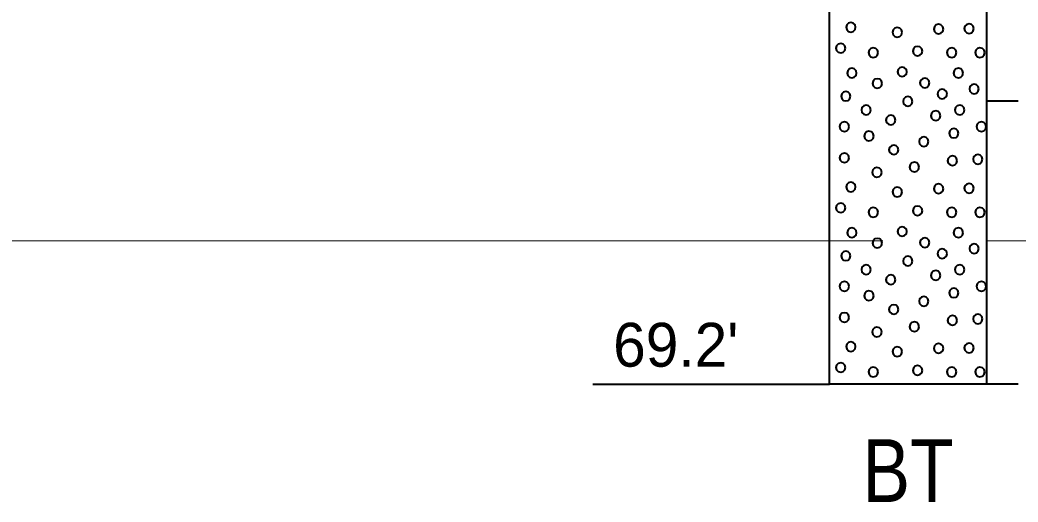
# Model space of a CAD drawing. Extents: x -582 to 653, y -817 to -3.
# Drawn here: x 14.65 to 30.53, y -558.29 to -550.62 of the extents above; entities that cross this region are included whole.
import ezdxf
from ezdxf.enums import TextEntityAlignment as Align

# ---------------------------------------------------------------- set-up
doc = ezdxf.new("R2010")
doc.units = 0
doc.header["$LTSCALE"] = 0.4
doc.layers.add('27', color=7, linetype='Continuous', lineweight=40)
doc.layers.add('7', color=7, linetype='Continuous', lineweight=13)

msp = doc.modelspace()

# ---------------------------------------------------------------- linework, layer by layer
at = {"layer": '27'}
for p, q in [((30.5287, -551.9128), (30.0287, -551.9128)), ((23.7613, -556.4128), (27.5287, -556.4128)), ((30.5287, -556.4128), (30.0287, -556.4128))]:
    msp.add_line(p, q, dxfattribs=at)
for points in [[(27.5287, -548.7128), (30.0287, -548.7128), (30.0287, -556.4128), (27.5287, -556.4128)], [(27.9445, -550.7362), (27.9343, -550.6981), (27.9064, -550.6702), (27.8683, -550.66), (27.8302, -550.6702), (27.8023, -550.6981), (27.7921, -550.7362), (27.8023, -550.7743), (27.8302, -550.8022), (27.8683, -550.8124), (27.9064, -550.8022), (27.9343, -550.7743)], [(28.6831, -550.8163), (28.6729, -550.7782), (28.645, -550.7503), (28.6069, -550.7401), (28.5688, -550.7503), (28.5409, -550.7782), (28.5307, -550.8163), (28.5409, -550.8544), (28.5688, -550.8823), (28.6069, -550.8925), (28.645, -550.8823), (28.6729, -550.8544)], [(29.3403, -550.7654), (29.3301, -550.7273), (29.3022, -550.6994), (29.2641, -550.6892), (29.226, -550.6994), (29.1982, -550.7273), (29.1879, -550.7654), (29.1982, -550.8035), (29.226, -550.8314), (29.2641, -550.8416), (29.3022, -550.8314), (29.3301, -550.8035)], [(29.826, -550.7578), (29.8158, -550.7197), (29.7879, -550.6918), (29.7498, -550.6816), (29.7117, -550.6918), (29.6838, -550.7197), (29.6736, -550.7578), (29.6838, -550.7959), (29.7117, -550.8238), (29.7498, -550.834), (29.7879, -550.8238), (29.8158, -550.7959)], [(27.783, -551.0693), (27.7728, -551.0312), (27.7449, -551.0033), (27.7068, -550.9931), (27.6687, -551.0033), (27.6408, -551.0312), (27.6306, -551.0693), (27.6408, -551.1074), (27.6687, -551.1353), (27.7068, -551.1455), (27.7449, -551.1353), (27.7728, -551.1074)], [(28.3017, -551.1392), (28.2915, -551.1011), (28.2636, -551.0732), (28.2255, -551.063), (28.1874, -551.0732), (28.1595, -551.1011), (28.1493, -551.1392), (28.1595, -551.1773), (28.1874, -551.2052), (28.2255, -551.2154), (28.2636, -551.2052), (28.2915, -551.1773)], [(29.006, -551.1163), (28.9958, -551.0782), (28.9679, -551.0503), (28.9298, -551.0401), (28.8917, -551.0503), (28.8638, -551.0782), (28.8536, -551.1163), (28.8638, -551.1544), (28.8917, -551.1823), (28.9298, -551.1925), (28.9679, -551.1823), (28.9958, -551.1544)], [(29.5488, -551.1392), (29.5386, -551.1011), (29.5107, -551.0732), (29.4726, -551.063), (29.4345, -551.0732), (29.4066, -551.1011), (29.3964, -551.1392), (29.4066, -551.1773), (29.4345, -551.2052), (29.4726, -551.2154), (29.5107, -551.2052), (29.5386, -551.1773)], [(29.9989, -551.1392), (29.9887, -551.1011), (29.9608, -551.0732), (29.9227, -551.063), (29.8846, -551.0732), (29.8567, -551.1011), (29.8465, -551.1392), (29.8567, -551.1773), (29.8846, -551.2052), (29.9227, -551.2154), (29.9608, -551.2052), (29.9887, -551.1773)], [(27.9606, -551.4655), (27.9504, -551.4274), (27.9225, -551.3995), (27.8844, -551.3893), (27.8463, -551.3995), (27.8184, -551.4274), (27.8082, -551.4655), (27.8184, -551.5036), (27.8463, -551.5314), (27.8844, -551.5417), (27.9225, -551.5314), (27.9504, -551.5036)], [(28.7616, -551.4459), (28.7513, -551.4078), (28.7235, -551.3799), (28.6854, -551.3697), (28.6473, -551.3799), (28.6194, -551.4078), (28.6092, -551.4459), (28.6194, -551.484), (28.6473, -551.5119), (28.6854, -551.5221), (28.7235, -551.5119), (28.7513, -551.484)], [(29.6552, -551.4655), (29.645, -551.4274), (29.6171, -551.3995), (29.579, -551.3893), (29.5409, -551.3995), (29.513, -551.4274), (29.5028, -551.4655), (29.513, -551.5036), (29.5409, -551.5315), (29.579, -551.5417), (29.6171, -551.5315), (29.645, -551.5036)], [(28.3655, -551.6307), (28.3553, -551.5926), (28.3274, -551.5647), (28.2893, -551.5545), (28.2512, -551.5647), (28.2233, -551.5926), (28.2131, -551.6307), (28.2233, -551.6688), (28.2512, -551.6967), (28.2893, -551.7069), (28.3274, -551.6967), (28.3553, -551.6688)], [(29.1206, -551.6217), (29.1104, -551.5836), (29.0825, -551.5557), (29.0444, -551.5455), (29.0063, -551.5557), (28.9784, -551.5836), (28.9682, -551.6217), (28.9784, -551.6598), (29.0063, -551.6877), (29.0444, -551.6979), (29.0825, -551.6877), (29.1104, -551.6598)], [(27.8644, -551.8333), (27.8542, -551.7952), (27.8263, -551.7673), (27.7882, -551.7571), (27.7501, -551.7673), (27.7222, -551.7952), (27.712, -551.8333), (27.7222, -551.8714), (27.7501, -551.8993), (27.7882, -551.9095), (27.8263, -551.8993), (27.8542, -551.8714)], [(29.3988, -551.799), (29.3886, -551.7609), (29.3607, -551.733), (29.3226, -551.7228), (29.2845, -551.733), (29.2566, -551.7609), (29.2464, -551.799), (29.2566, -551.8371), (29.2845, -551.865), (29.3226, -551.8752), (29.3607, -551.865), (29.3886, -551.8371)], [(29.9061, -551.7176), (29.8959, -551.6795), (29.868, -551.6516), (29.8299, -551.6414), (29.7918, -551.6516), (29.7639, -551.6795), (29.7537, -551.7176), (29.7639, -551.7557), (29.7918, -551.7836), (29.8299, -551.7938), (29.868, -551.7836), (29.8959, -551.7557)], [(28.8505, -551.9165), (28.8403, -551.8784), (28.8124, -551.8505), (28.7743, -551.8403), (28.7362, -551.8505), (28.7083, -551.8784), (28.6981, -551.9165), (28.7083, -551.9546), (28.7362, -551.9825), (28.7743, -551.9927), (28.8124, -551.9825), (28.8403, -551.9546)], [(28.1873, -552.052), (28.1771, -552.0139), (28.1492, -551.986), (28.1111, -551.9758), (28.073, -551.986), (28.0451, -552.0139), (28.0349, -552.052), (28.0451, -552.0901), (28.073, -552.118), (28.1111, -552.1282), (28.1492, -552.118), (28.1771, -552.0901)], [(29.2946, -552.1448), (29.2844, -552.1067), (29.2565, -552.0788), (29.2184, -552.0686), (29.1803, -552.0788), (29.1524, -552.1067), (29.1422, -552.1448), (29.1524, -552.1829), (29.1803, -552.2108), (29.2184, -552.221), (29.2565, -552.2108), (29.2844, -552.1829)], [(29.676, -552.052), (29.6658, -552.0139), (29.6379, -551.986), (29.5998, -551.9758), (29.5617, -551.986), (29.5338, -552.0139), (29.5236, -552.052), (29.5338, -552.0901), (29.5617, -552.118), (29.5998, -552.1282), (29.6379, -552.118), (29.6658, -552.0901)], [(27.8415, -552.3177), (27.8313, -552.2796), (27.8034, -552.2517), (27.7653, -552.2415), (27.7272, -552.2517), (27.6993, -552.2796), (27.6891, -552.3177), (27.6993, -552.3558), (27.7272, -552.3837), (27.7653, -552.3939), (27.8034, -552.3837), (27.8313, -552.3558)], [(28.5789, -552.2134), (28.5686, -552.1753), (28.5408, -552.1474), (28.5027, -552.1372), (28.4646, -552.1474), (28.4367, -552.1753), (28.4265, -552.2134), (28.4367, -552.2515), (28.4646, -552.2794), (28.5027, -552.2896), (28.5408, -552.2794), (28.5686, -552.2515)], [(30.0217, -552.3177), (30.0115, -552.2796), (29.9836, -552.2517), (29.9455, -552.2415), (29.9074, -552.2517), (29.8796, -552.2796), (29.8693, -552.3177), (29.8796, -552.3558), (29.9074, -552.3837), (29.9455, -552.3939), (29.9836, -552.3837), (30.0115, -552.3558)], [(28.2331, -552.4677), (28.2229, -552.4296), (28.195, -552.4017), (28.1569, -552.3915), (28.1188, -552.4017), (28.0909, -552.4296), (28.0807, -552.4677), (28.0909, -552.5058), (28.1188, -552.5337), (28.1569, -552.5439), (28.195, -552.5337), (28.2229, -552.5058)], [(29.5832, -552.4219), (29.5729, -552.3838), (29.5451, -552.3559), (29.507, -552.3457), (29.4689, -552.3559), (29.441, -552.3838), (29.4308, -552.4219), (29.441, -552.46), (29.4689, -552.4879), (29.507, -552.4981), (29.5451, -552.4879), (29.5729, -552.46)], [(29.1052, -552.5554), (29.095, -552.5173), (29.0671, -552.4894), (29.029, -552.4792), (28.9909, -552.4894), (28.963, -552.5173), (28.9528, -552.5554), (28.963, -552.5935), (28.9909, -552.6214), (29.029, -552.6316), (29.0671, -552.6214), (29.095, -552.5935)], [(27.8415, -552.8135), (27.8313, -552.7754), (27.8034, -552.7475), (27.7653, -552.7373), (27.7272, -552.7475), (27.6993, -552.7754), (27.6891, -552.8135), (27.6993, -552.8516), (27.7272, -552.8794), (27.7653, -552.8897), (27.8034, -552.8794), (27.8313, -552.8516)], [(28.6272, -552.6863), (28.617, -552.6482), (28.5891, -552.6203), (28.551, -552.6101), (28.5129, -552.6203), (28.485, -552.6482), (28.4748, -552.6863), (28.485, -552.7244), (28.5129, -552.7523), (28.551, -552.7625), (28.5891, -552.7523), (28.617, -552.7244)], [(28.9551, -552.9609), (28.9449, -552.9228), (28.917, -552.8949), (28.8789, -552.8847), (28.8408, -552.8949), (28.813, -552.9228), (28.8027, -552.9609), (28.813, -552.999), (28.8408, -553.0269), (28.8789, -553.0371), (28.917, -553.0269), (28.9449, -552.999)], [(29.5603, -552.8605), (29.5501, -552.8224), (29.5222, -552.7945), (29.4841, -552.7843), (29.446, -552.7945), (29.4181, -552.8224), (29.4079, -552.8605), (29.4181, -552.8986), (29.446, -552.9265), (29.4841, -552.9367), (29.5222, -552.9265), (29.5501, -552.8986)], [(29.9645, -552.8363), (29.9543, -552.7982), (29.9264, -552.7704), (29.8883, -552.7601), (29.8502, -552.7704), (29.8223, -552.7982), (29.8121, -552.8363), (29.8223, -552.8744), (29.8502, -552.9023), (29.8883, -552.9125), (29.9264, -552.9023), (29.9543, -552.8744)], [(28.3602, -553.0448), (28.35, -553.0067), (28.3221, -552.9788), (28.284, -552.9686), (28.2459, -552.9788), (28.218, -553.0067), (28.2078, -553.0448), (28.218, -553.0829), (28.2459, -553.1108), (28.284, -553.121), (28.3221, -553.1108), (28.35, -553.0829)], [(27.9445, -553.2762), (27.9343, -553.2381), (27.9064, -553.2102), (27.8683, -553.2), (27.8302, -553.2102), (27.8023, -553.2381), (27.7921, -553.2762), (27.8023, -553.3143), (27.8302, -553.3422), (27.8683, -553.3524), (27.9064, -553.3422), (27.9343, -553.3143)], [(28.6831, -553.3563), (28.6729, -553.3182), (28.645, -553.2903), (28.6069, -553.2801), (28.5688, -553.2903), (28.5409, -553.3182), (28.5307, -553.3563), (28.5409, -553.3944), (28.5688, -553.4223), (28.6069, -553.4325), (28.645, -553.4223), (28.6729, -553.3944)], [(29.3403, -553.3054), (29.3301, -553.2673), (29.3022, -553.2394), (29.2641, -553.2292), (29.226, -553.2394), (29.1982, -553.2673), (29.1879, -553.3054), (29.1982, -553.3435), (29.226, -553.3714), (29.2641, -553.3816), (29.3022, -553.3714), (29.3301, -553.3435)], [(29.826, -553.2978), (29.8158, -553.2597), (29.7879, -553.2318), (29.7498, -553.2216), (29.7117, -553.2318), (29.6838, -553.2597), (29.6736, -553.2978), (29.6838, -553.3359), (29.7117, -553.3638), (29.7498, -553.374), (29.7879, -553.3638), (29.8158, -553.3359)], [(27.783, -553.6093), (27.7728, -553.5712), (27.7449, -553.5433), (27.7068, -553.5331), (27.6687, -553.5433), (27.6408, -553.5712), (27.6306, -553.6093), (27.6408, -553.6474), (27.6687, -553.6753), (27.7068, -553.6855), (27.7449, -553.6753), (27.7728, -553.6474)], [(28.3017, -553.6792), (28.2915, -553.6411), (28.2636, -553.6132), (28.2255, -553.603), (28.1874, -553.6132), (28.1595, -553.6411), (28.1493, -553.6792), (28.1595, -553.7173), (28.1874, -553.7452), (28.2255, -553.7554), (28.2636, -553.7452), (28.2915, -553.7173)], [(29.006, -553.6563), (28.9958, -553.6182), (28.9679, -553.5903), (28.9298, -553.5801), (28.8917, -553.5903), (28.8638, -553.6182), (28.8536, -553.6563), (28.8638, -553.6944), (28.8917, -553.7223), (28.9298, -553.7325), (28.9679, -553.7223), (28.9958, -553.6944)], [(29.5488, -553.6792), (29.5386, -553.6411), (29.5107, -553.6132), (29.4726, -553.603), (29.4345, -553.6132), (29.4066, -553.6411), (29.3964, -553.6792), (29.4066, -553.7173), (29.4345, -553.7452), (29.4726, -553.7554), (29.5107, -553.7452), (29.5386, -553.7173)], [(29.9989, -553.6792), (29.9887, -553.6411), (29.9608, -553.6132), (29.9227, -553.603), (29.8846, -553.6132), (29.8567, -553.6411), (29.8465, -553.6792), (29.8567, -553.7173), (29.8846, -553.7452), (29.9227, -553.7554), (29.9608, -553.7452), (29.9887, -553.7173)], [(27.9606, -554.0055), (27.9504, -553.9674), (27.9225, -553.9395), (27.8844, -553.9293), (27.8463, -553.9395), (27.8184, -553.9674), (27.8082, -554.0055), (27.8184, -554.0436), (27.8463, -554.0714), (27.8844, -554.0817), (27.9225, -554.0714), (27.9504, -554.0436)], [(28.7616, -553.9859), (28.7513, -553.9478), (28.7235, -553.9199), (28.6854, -553.9097), (28.6473, -553.9199), (28.6194, -553.9478), (28.6092, -553.9859), (28.6194, -554.024), (28.6473, -554.0519), (28.6854, -554.0621), (28.7235, -554.0519), (28.7513, -554.024)], [(29.6552, -554.0055), (29.645, -553.9674), (29.6171, -553.9395), (29.579, -553.9293), (29.5409, -553.9395), (29.513, -553.9674), (29.5028, -554.0055), (29.513, -554.0436), (29.5409, -554.0715), (29.579, -554.0817), (29.6171, -554.0715), (29.645, -554.0436)], [(28.3655, -554.1707), (28.3553, -554.1326), (28.3274, -554.1047), (28.2893, -554.0945), (28.2512, -554.1047), (28.2233, -554.1326), (28.2131, -554.1707), (28.2233, -554.2088), (28.2512, -554.2367), (28.2893, -554.2469), (28.3274, -554.2367), (28.3553, -554.2088)], [(29.1206, -554.1617), (29.1104, -554.1236), (29.0825, -554.0957), (29.0444, -554.0855), (29.0063, -554.0957), (28.9784, -554.1236), (28.9682, -554.1617), (28.9784, -554.1998), (29.0063, -554.2277), (29.0444, -554.2379), (29.0825, -554.2277), (29.1104, -554.1998)], [(27.8644, -554.3733), (27.8542, -554.3352), (27.8263, -554.3073), (27.7882, -554.2971), (27.7501, -554.3073), (27.7222, -554.3352), (27.712, -554.3733), (27.7222, -554.4114), (27.7501, -554.4393), (27.7882, -554.4495), (27.8263, -554.4393), (27.8542, -554.4114)], [(29.3988, -554.339), (29.3886, -554.3009), (29.3607, -554.273), (29.3226, -554.2628), (29.2845, -554.273), (29.2566, -554.3009), (29.2464, -554.339), (29.2566, -554.3771), (29.2845, -554.405), (29.3226, -554.4152), (29.3607, -554.405), (29.3886, -554.3771)], [(29.9061, -554.2576), (29.8959, -554.2195), (29.868, -554.1916), (29.8299, -554.1814), (29.7918, -554.1916), (29.7639, -554.2195), (29.7537, -554.2576), (29.7639, -554.2957), (29.7918, -554.3236), (29.8299, -554.3338), (29.868, -554.3236), (29.8959, -554.2957)], [(28.8505, -554.4565), (28.8403, -554.4184), (28.8124, -554.3905), (28.7743, -554.3803), (28.7362, -554.3905), (28.7083, -554.4184), (28.6981, -554.4565), (28.7083, -554.4946), (28.7362, -554.5225), (28.7743, -554.5327), (28.8124, -554.5225), (28.8403, -554.4946)], [(28.1873, -554.592), (28.1771, -554.5539), (28.1492, -554.526), (28.1111, -554.5158), (28.073, -554.526), (28.0451, -554.5539), (28.0349, -554.592), (28.0451, -554.6301), (28.073, -554.658), (28.1111, -554.6682), (28.1492, -554.658), (28.1771, -554.6301)], [(29.2946, -554.6848), (29.2844, -554.6467), (29.2565, -554.6188), (29.2184, -554.6086), (29.1803, -554.6188), (29.1524, -554.6467), (29.1422, -554.6848), (29.1524, -554.7229), (29.1803, -554.7508), (29.2184, -554.761), (29.2565, -554.7508), (29.2844, -554.7229)], [(29.676, -554.592), (29.6658, -554.5539), (29.6379, -554.526), (29.5998, -554.5158), (29.5617, -554.526), (29.5338, -554.5539), (29.5236, -554.592), (29.5338, -554.6301), (29.5617, -554.658), (29.5998, -554.6682), (29.6379, -554.658), (29.6658, -554.6301)], [(27.8415, -554.8577), (27.8313, -554.8196), (27.8034, -554.7917), (27.7653, -554.7815), (27.7272, -554.7917), (27.6993, -554.8196), (27.6891, -554.8577), (27.6993, -554.8958), (27.7272, -554.9237), (27.7653, -554.9339), (27.8034, -554.9237), (27.8313, -554.8958)], [(28.5789, -554.7534), (28.5686, -554.7153), (28.5408, -554.6874), (28.5027, -554.6772), (28.4646, -554.6874), (28.4367, -554.7153), (28.4265, -554.7534), (28.4367, -554.7915), (28.4646, -554.8194), (28.5027, -554.8296), (28.5408, -554.8194), (28.5686, -554.7915)], [(30.0217, -554.8577), (30.0115, -554.8196), (29.9836, -554.7917), (29.9455, -554.7815), (29.9074, -554.7917), (29.8796, -554.8196), (29.8693, -554.8577), (29.8796, -554.8958), (29.9074, -554.9237), (29.9455, -554.9339), (29.9836, -554.9237), (30.0115, -554.8958)], [(28.2331, -555.0077), (28.2229, -554.9696), (28.195, -554.9417), (28.1569, -554.9315), (28.1188, -554.9417), (28.0909, -554.9696), (28.0807, -555.0077), (28.0909, -555.0458), (28.1188, -555.0737), (28.1569, -555.0839), (28.195, -555.0737), (28.2229, -555.0458)], [(29.5832, -554.9619), (29.5729, -554.9238), (29.5451, -554.8959), (29.507, -554.8857), (29.4689, -554.8959), (29.441, -554.9238), (29.4308, -554.9619), (29.441, -555), (29.4689, -555.0279), (29.507, -555.0381), (29.5451, -555.0279), (29.5729, -555)], [(29.1052, -555.0954), (29.095, -555.0573), (29.0671, -555.0294), (29.029, -555.0192), (28.9909, -555.0294), (28.963, -555.0573), (28.9528, -555.0954), (28.963, -555.1335), (28.9909, -555.1614), (29.029, -555.1716), (29.0671, -555.1614), (29.095, -555.1335)], [(27.8415, -555.3535), (27.8313, -555.3154), (27.8034, -555.2875), (27.7653, -555.2773), (27.7272, -555.2875), (27.6993, -555.3154), (27.6891, -555.3535), (27.6993, -555.3916), (27.7272, -555.4194), (27.7653, -555.4297), (27.8034, -555.4194), (27.8313, -555.3916)], [(28.6272, -555.2263), (28.617, -555.1882), (28.5891, -555.1603), (28.551, -555.1501), (28.5129, -555.1603), (28.485, -555.1882), (28.4748, -555.2263), (28.485, -555.2644), (28.5129, -555.2923), (28.551, -555.3025), (28.5891, -555.2923), (28.617, -555.2644)], [(28.9551, -555.5009), (28.9449, -555.4628), (28.917, -555.4349), (28.8789, -555.4247), (28.8408, -555.4349), (28.813, -555.4628), (28.8027, -555.5009), (28.813, -555.539), (28.8408, -555.5669), (28.8789, -555.5771), (28.917, -555.5669), (28.9449, -555.539)], [(29.5603, -555.4005), (29.5501, -555.3624), (29.5222, -555.3345), (29.4841, -555.3243), (29.446, -555.3345), (29.4181, -555.3624), (29.4079, -555.4005), (29.4181, -555.4386), (29.446, -555.4665), (29.4841, -555.4767), (29.5222, -555.4665), (29.5501, -555.4386)], [(29.9645, -555.3763), (29.9543, -555.3382), (29.9264, -555.3104), (29.8883, -555.3001), (29.8502, -555.3104), (29.8223, -555.3382), (29.8121, -555.3763), (29.8223, -555.4144), (29.8502, -555.4423), (29.8883, -555.4525), (29.9264, -555.4423), (29.9543, -555.4144)], [(28.3602, -555.5848), (28.35, -555.5467), (28.3221, -555.5188), (28.284, -555.5086), (28.2459, -555.5188), (28.218, -555.5467), (28.2078, -555.5848), (28.218, -555.6229), (28.2459, -555.6508), (28.284, -555.661), (28.3221, -555.6508), (28.35, -555.6229)], [(27.9445, -555.8162), (27.9343, -555.7781), (27.9064, -555.7502), (27.8683, -555.74), (27.8302, -555.7502), (27.8023, -555.7781), (27.7921, -555.8162), (27.8023, -555.8543), (27.8302, -555.8822), (27.8683, -555.8924), (27.9064, -555.8822), (27.9343, -555.8543)], [(29.826, -555.8378), (29.8158, -555.7997), (29.7879, -555.7718), (29.7498, -555.7616), (29.7117, -555.7718), (29.6838, -555.7997), (29.6736, -555.8378), (29.6838, -555.8759), (29.7117, -555.9038), (29.7498, -555.914), (29.7879, -555.9038), (29.8158, -555.8759)], [(28.6831, -555.8963), (28.6729, -555.8582), (28.645, -555.8303), (28.6069, -555.8201), (28.5688, -555.8303), (28.5409, -555.8582), (28.5307, -555.8963), (28.5409, -555.9344), (28.5688, -555.9623), (28.6069, -555.9725), (28.645, -555.9623), (28.6729, -555.9344)], [(29.3403, -555.8454), (29.3301, -555.8073), (29.3022, -555.7794), (29.2641, -555.7692), (29.226, -555.7794), (29.1982, -555.8073), (29.1879, -555.8454), (29.1982, -555.8835), (29.226, -555.9114), (29.2641, -555.9216), (29.3022, -555.9114), (29.3301, -555.8835)], [(27.783, -556.1493), (27.7728, -556.1112), (27.7449, -556.0833), (27.7068, -556.0731), (27.6687, -556.0833), (27.6408, -556.1112), (27.6306, -556.1493), (27.6408, -556.1874), (27.6687, -556.2153), (27.7068, -556.2255), (27.7449, -556.2153), (27.7728, -556.1874)], [(28.3017, -556.2192), (28.2915, -556.1811), (28.2636, -556.1532), (28.2255, -556.143), (28.1874, -556.1532), (28.1595, -556.1811), (28.1493, -556.2192), (28.1595, -556.2573), (28.1874, -556.2852), (28.2255, -556.2954), (28.2636, -556.2852), (28.2915, -556.2573)], [(29.006, -556.1963), (28.9958, -556.1582), (28.9679, -556.1303), (28.9298, -556.1201), (28.8917, -556.1303), (28.8638, -556.1582), (28.8536, -556.1963), (28.8638, -556.2344), (28.8917, -556.2623), (28.9298, -556.2725), (28.9679, -556.2623), (28.9958, -556.2344)], [(29.5488, -556.2192), (29.5386, -556.1811), (29.5107, -556.1532), (29.4726, -556.143), (29.4345, -556.1532), (29.4066, -556.1811), (29.3964, -556.2192), (29.4066, -556.2573), (29.4345, -556.2852), (29.4726, -556.2954), (29.5107, -556.2852), (29.5386, -556.2573)], [(29.9989, -556.2192), (29.9887, -556.1811), (29.9608, -556.1532), (29.9227, -556.143), (29.8846, -556.1532), (29.8567, -556.1811), (29.8465, -556.2192), (29.8567, -556.2573), (29.8846, -556.2852), (29.9227, -556.2954), (29.9608, -556.2852), (29.9887, -556.2573)]]:
    msp.add_lwpolyline(points, close=True, dxfattribs=at)
at = {"layer": '7'}
for p, q in [((-23.9857, -554.1328), (27.5287, -554.1328)), ((-22.9713, -554.1328), (28.379, -554.1328)), ((30.0287, -554.1328), (67.308, -554.1328))]:
    msp.add_line(p, q, dxfattribs=at)

# ---------------------------------------------------------------- texts
at = {"layer": '27'}
msp.add_text("69.2'", height=0.6976, dxfattribs=at).set_placement((24.0852, -556.1363))
at = {"layer": '27', "width": 0.85}
msp.add_text('BT', height=1, dxfattribs=at).set_placement((28.7786, -558.2896), align=Align.CENTER)

doc.saveas('drawing.dxf')
